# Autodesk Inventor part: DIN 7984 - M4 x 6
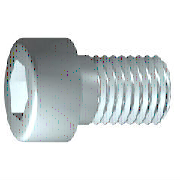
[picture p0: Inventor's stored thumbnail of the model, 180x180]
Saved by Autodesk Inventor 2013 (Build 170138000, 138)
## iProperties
IsCustomPart: 0
Created: 2012-02
Part Number: DIN 7984 - M4 x 6
Material: Steel, Mild
Description: Cylinder Head Cap Screw
Document SubType Name: Modeling
Standard: DIN 7984
Designer: rYan
Standard Revision: 1985
Standards Organization: DIN
Language: en-US
Size Designation: M4 x 6
Categories: <MemberInstance><Categories><Category DisplayName="Fasteners" InternalName="e4da775c-781d-43d5-af7c-5136215cf5a6" Mnemonic="FSTN"><Category DisplayName="Bolts"
Density: 7.86 g/cm^3
Mass: 1.31382 g
Surface Area: 2.27551 cm^2
Volume: 0.167153 cm^3
Author: rYan
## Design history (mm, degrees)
sketch "Sketch1"
  geometry: L1 (0.333, 0)-(6, 0); L2 (6, 0)-(6, 2); L3 (6, 2)-(2.1, 2); L4 (2.1, 2)-(1.67, 2); L5 (1.67, 2)-(0, 2); L6 (0, 2)-(0, 3.5); L7 (0, 3.5)-(-2.8, 3.5); L8 (-2.8, 3.5)-(-2.8, 1.443); L9 (-2.8, 1.443)-(-0.5, 1.443); L10 (-0.5, 1.443)-(0.333, 0); L11 (-4.56, 0)-(7.76, 0) reference; L12 (0, -0.7)-(0, 4.2) reference; L13 (2.1, 2)-(0, 2)
  constraints: 22 end point, 6 parallel, 2 collinear, 2 perpendicular, 1 horizontal, 1 point on line
  dimensions: "d1" = 3.9 distance from line of L3.end L2 (= GEL); "d2" = 0.42952 distance of L4.end L3.end (computed from GAL); "d3" = 2.8 distance between parallel lines of L8 L6 (= KOH); "d4" = 2.3 distance of L8.end L9.end (= INTI); "d5" = 60 deg angle of L10 L1; "d6" = 4 diameter of L3 L1 (= GD); "d7" = 4 diameter of L5 L1 (= BDM); "d8" = 2.88675 diameter of L9 L1 (= 1.1547 x SW); "d9" = 7 diameter of L7 L1 (= KOD); "d26" = 6 distance between parallel lines of L12 L2 (= NLG)
revolve "Body" sketch "Sketch1" stored, may be unused: angle "d10" = 90 deg
sketch "Sketch2"
  geometry: L1 (0, -4.9)-(0, 4.9) reference; L2 (-4.9, 0)-(4.9, 0) reference; L3 (1.443, 0)-(0.722, -1.25); L4 (0.722, -1.25)-(-0.722, -1.25); L5 (-0.722, -1.25)-(-1.443, 0); L6 (-1.443, 0)-(-0.722, 1.25); L7 (-0.722, 1.25)-(0.722, 1.25); L8 (0.722, 1.25)-(1.443, 0); 2 further points
  constraints: 12 end point, 1 coincident, 1 horizontal alignment, 1 point on line, 12 other
extrude "Slot" join sketch "Sketch2" stored distance "d11" = 10; taper "d12" = 0 deg
workplane "Work Plane1"
fillet "Fillet2" dims "d30" = 0.1 (= R)
body "Solid1"
fillet "Fillet1" dims "d17" = 0.4 (= RR)
feature "Thread" dims "d13" = 3.9 (= GEL), "d14" = 0
chamfer "Chamfer1" distance "d15" = 0.42941 (= -0.5 x SPD + 0.5 x GD); stored, may be unused: second distance "d16" = 0.42941 (= GUL), angle "d27" = 45 deg
other parameters: "GD" = 4 (= NND) [user parameter; used in 2 equation terms], "NLG" = 6 [user parameter; used in 1 equation term], "GEL" = 3.9 [user parameter; used in 2 equation terms], "KOD" = 7 [user parameter; used in 1 equation term], "KOH" = 2.8 [user parameter; used in 1 equation term], "INTI" = 2.3 [user parameter; used in 1 equation term], "GAL" = 0.42941 (= 0.61345 x PTC) [user parameter; used in 1 equation term], "GUL" = 0.42941 (= 0.61345 x PTC) [user parameter; used in 1 equation term], "BDM" = 4 (= NND) [user parameter; used in 1 equation term], "SW" = 2.5 [user parameter; used in 2 equation terms], "RR" = 0.4 [user parameter; used in 1 equation term], "SPD" = 3.14117 (= NND - 1.2269 x PTC) [user parameter; used in 1 equation term], "d19" = 0, "d28" = 0, "d29" = 0, "R" = 0.1 [user parameter; used in 1 equation term], "TOA" = 30 deg [user parameter], "GD1" = 3.14117 (= THREADDIA - 1.2269 x PTC) [user parameter], "THREADDIA" = 4 [user parameter; used in 1 equation term], "FAWI" = 45 deg [user parameter], "ANG" = 120 deg [user parameter], "TPU" = 14.28571 (computed from PTC) [user parameter], "PTC" = 0.7 [user parameter; used in 5 equation terms], "NND" = 4 [user parameter; used in 3 equation terms], "E0" = 2.8875 (= 1.155 x SW) [user parameter]
